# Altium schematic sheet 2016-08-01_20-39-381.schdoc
size 374 x 119 mm; SheetNumber: 1; SheetTotal: 1
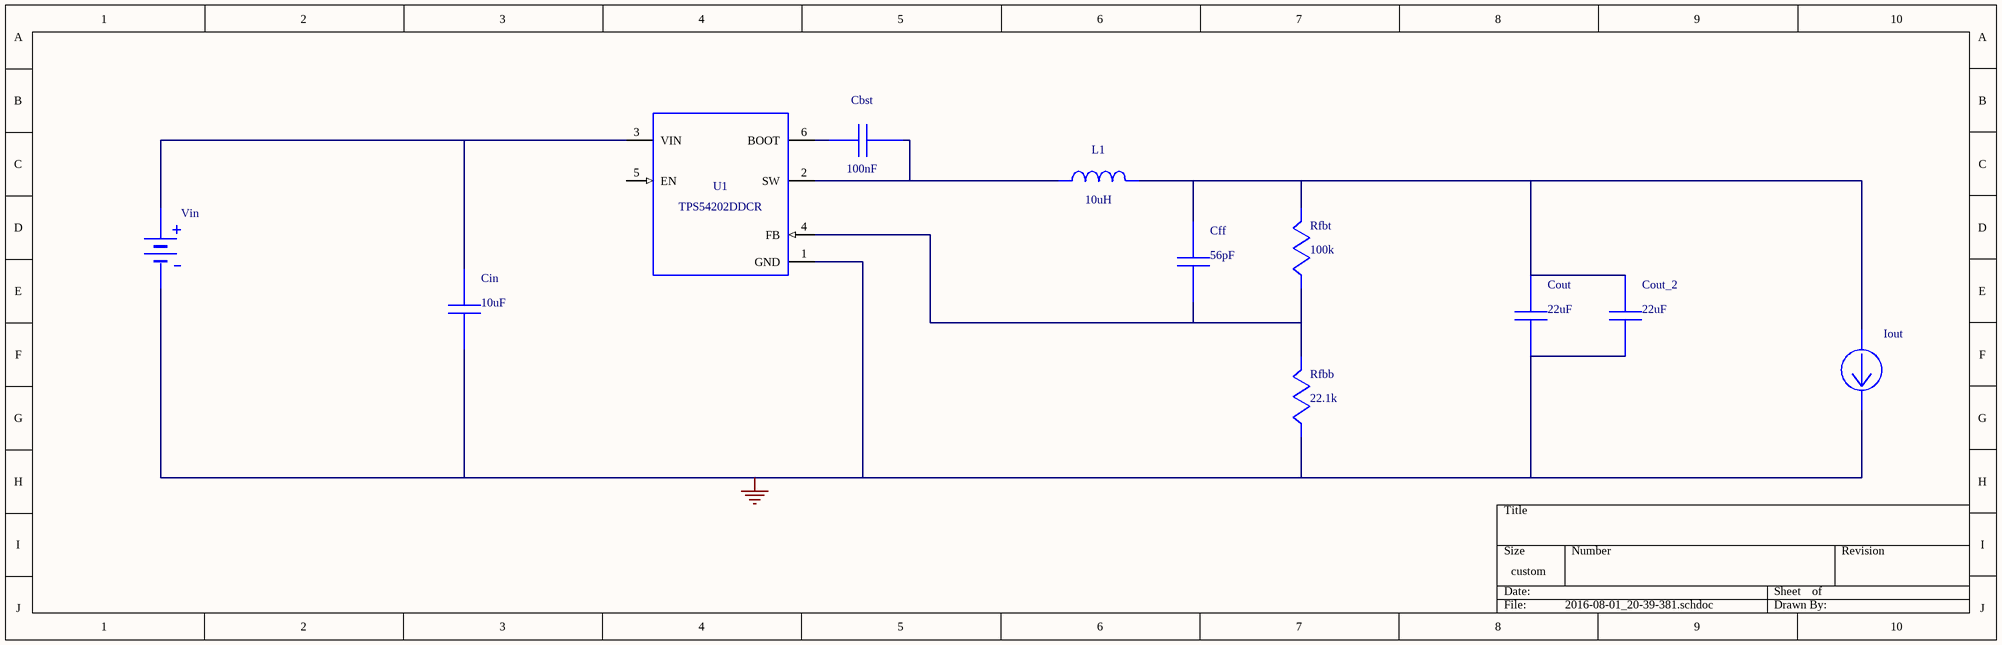
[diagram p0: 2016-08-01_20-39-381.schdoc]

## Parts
Cbst  value 100nF  (hidden comment: C0805C104K5RACTU)
Cff  value 56pF  (hidden comment: C0201C560J3GACTU)
Cin  value 10uF  (hidden comment: GRM32ER71J106KA12L)
Cout  value 22uF  (hidden comment: C4532X5R1E226M)
Cout_2  value 22uF  (hidden comment: C4532X5R1E226M)
Iout  WB_CURRENT_LOAD  (value not drawn)
L1  value 10uH  (hidden comment: SRN6045-100M)
Rfbb  value 22.1k  (hidden comment: CRCW040222K1FKED)
Rfbt  value 100k  (hidden comment: CRCW0402100KFKED)
U1  TPS54202DDCR
Vin  WB_BATTERY  (value not drawn)

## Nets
0: Cin.2 Cout.2 Cout_2.2 Iout.2(-) Rfbb.2 U1.1(GND) Vin.2(-)
NetCbst_1: Cbst.1 U1.6(BOOT)
NetCbst_2: Cbst.2 L1.1 U1.2(SW)
NetCff_1: Cff.1 Cout.1 Cout_2.1 Iout.1(+) L1.2 Rfbt.1
NetCff_2: Cff.2 Rfbb.1 Rfbt.2 U1.4(FB)
NetCin_1: Cin.1 U1.3(VIN) Vin.1(+)

Not connected (* = marked no-connect by the designer): U1 5(EN)

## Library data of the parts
Cbst = C0805C104K5RACTU: Manufacturer Name: Kemet
Cff = C0201C560J3GACTU: Manufacturer Name: Kemet
Cin = GRM32ER71J106KA12L: GRM32ER71J106KA1; Manufacturer Name: MuRata
Cout Cout_2 = C4532X5R1E226M: Manufacturer Name: TDK
L1 = SRN6045-100M: Manufacturer Name: Bourns
Rfbb = CRCW040222K1FKED: Manufacturer Name: Vishay-Dale
Rfbt = CRCW0402100KFKED: Manufacturer Name: Vishay-Dale
U1 = TPS54202DDCR: Manufacturer Name: Texas Instruments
